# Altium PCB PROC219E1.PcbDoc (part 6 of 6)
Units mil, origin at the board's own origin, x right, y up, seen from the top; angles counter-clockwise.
Board outline 5354.33 x 5354.33 mil, 4 copper layers (Top Layer, Inner Layer 1, Inner Layer 2, Bottom Layer), stack 62.449 mil thick; 579 components, 299 nets, 1709 pads, 802 vias.
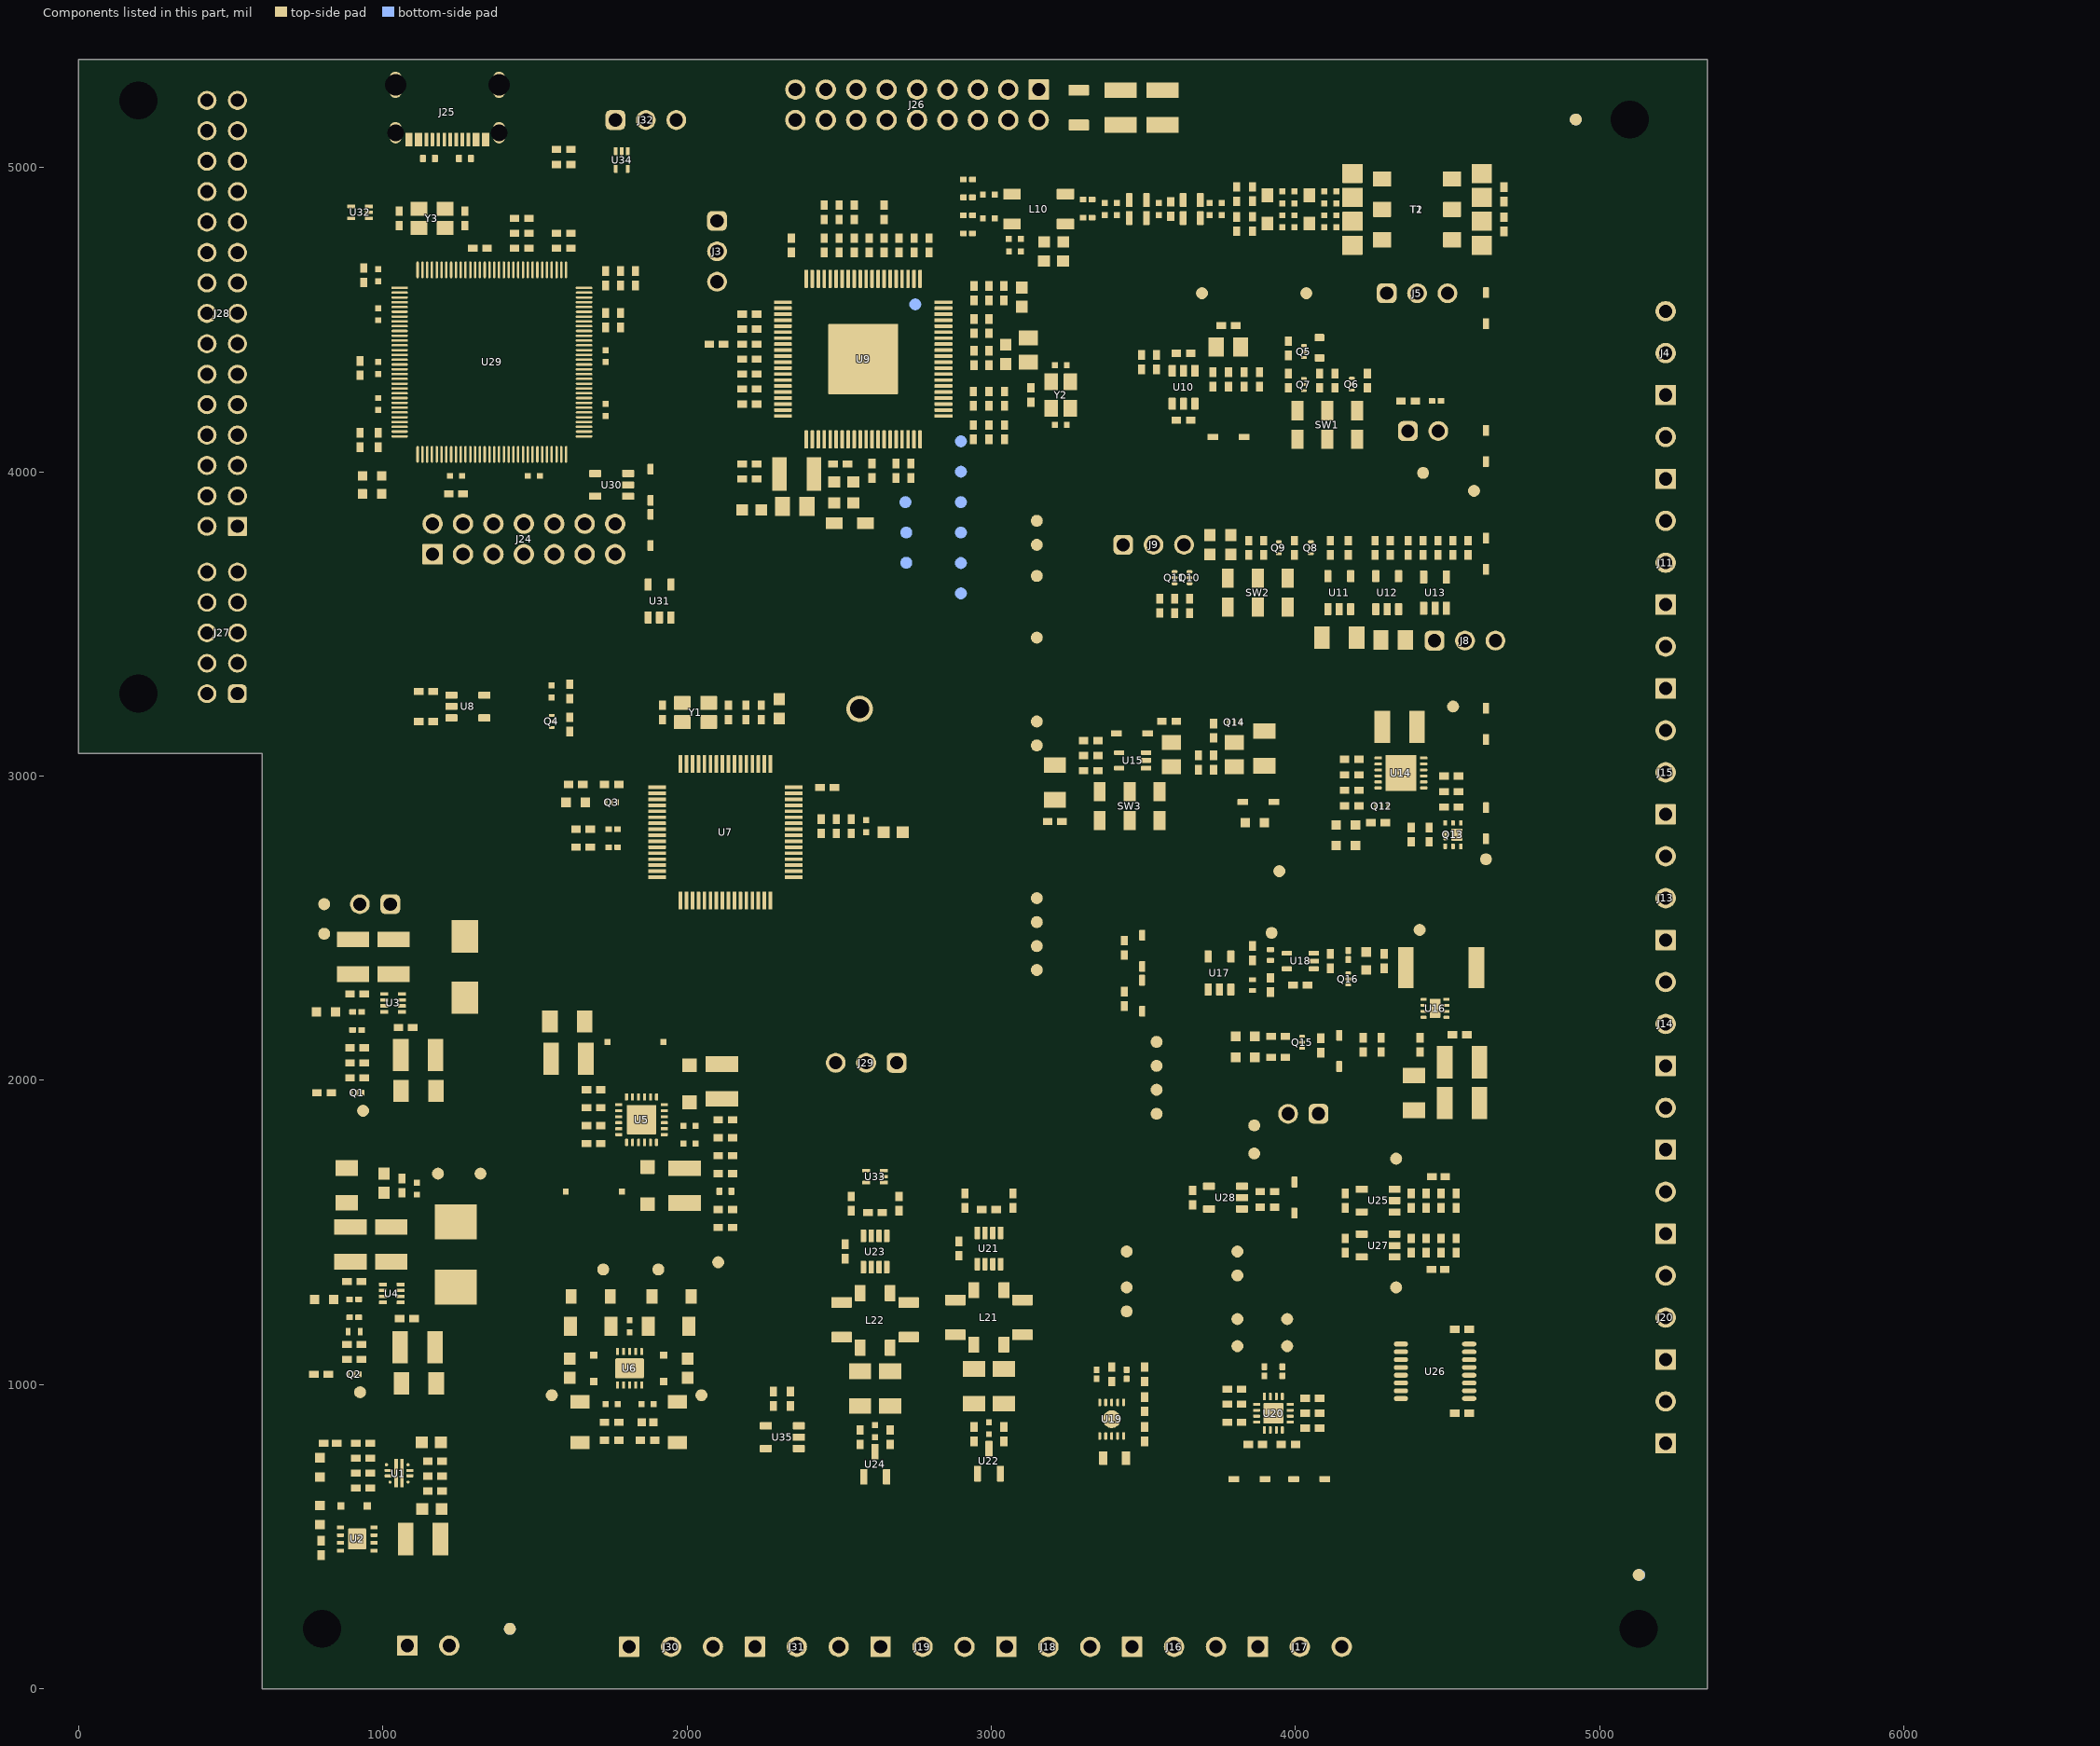
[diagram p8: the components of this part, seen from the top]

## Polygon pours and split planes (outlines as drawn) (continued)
+14V_EXT on Top Layer "TOP_LAYER_+14V_EXT_P077" (solid, remove dead copper, pour order 77): 1862.2,1090.55 1870.08,1082.68 1940.94,1082.68 1940.94,1393.7 1933.07,1401.64 1838.65,1401.64 1830.71,1393.7 1830.71,1149.61 1822.83,1141.73 1822.83,1090.55 1822.83,1141.73 1822.83,1090.55
-14V_EXT on Top Layer "TOP_LAYER_-14V_EXT_P075" (solid, remove dead copper, pour order 75): 1783.68,1091.09 1760.38,1091.09 1751.97,1082.68 1677.17,1082.68 1677.17,1393.7 1685.04,1401.57 1775.59,1401.57 1783.46,1393.7 1783.46,1090.55
NetD11_1 on Top Layer "TOP_LAYER_NETD11_1_P072" (solid, remove dead copper, pour order 72): 1830.56,1812.2 1795.12,1812.2 1720.32,1737.4 1720.32,1528.73 1887.42,1528.73 1897.48,1538.79 1897.48,1615.35 1830.56,1682.28
NetD7_2 on Top Layer "TOP_LAYER_NETD7_2_P070" (solid, remove dead copper, pour order 70): 1909.3,1910.62 1889.61,1930.31 1889.61,1979.52 1860.08,2009.05 1860.08,2235.43 1948.67,2235.43 2037.25,2146.85 2037.25,2015.25 1932.62,1910.62
NetC28_2 on Top Layer "TOP_LAYER_NETC28_2_P063" (solid, remove dead copper, pour order 63): 1830.56,1961.86 1823.59,1968.83 1823.59,2232.55 1820.71,2235.43 1623.86,2235.43 1623.86,1999.21 1633.71,1989.36 1682.92,1989.36 1692.76,1979.52 1692.76,1890.94 1751.82,1890.94 1751.82,1930.31 1830.56,1930.31
5V on Top Layer "TOP_LAYER_5V_P015" (solid, remove dead copper, pour order 15): 984.25,2539.37 984.25,2618.11 856.3,2618.11 856.3,2389.58 1318.9,2389.58 1318.9,2539.37
NetC8_2 on Top Layer "TOP_LAYER_NETC8_2_P036" (solid, remove dead copper, pour order 36): 1047.24,2273.62 1047.24,2253.94 1096.46,2253.94 1135.83,2214.57 1312.99,2214.57 1312.99,2332.68 1135.83,2332.68 1076.77,2273.62
NetC9_2 on Top Layer "TOP_LAYER_NETC9_2_P062" (solid, remove dead copper, pour order 62): 1147.75,1925.42 1147.75,1995.95 1086.61,2057.09 1086.61,2185.04 1076.77,2234.25 1047.24,2234.25 1047.24,2253.94 1092.45,2253.94 1234.25,2112.14 1234.25,2017.72 1234.25,1925.42
3.3V on Top Layer "TOP_LAYER_3.3V_P017" (solid, remove dead copper, pour order 17): 842.52,1653.54 1112.2,1653.54 1151.57,1614.17 1230.32,1614.17 1230.32,1740.16 842.52,1740.16
3V3_FB on Top Layer "TOP_LAYER_3V3_FB_P060" (solid, remove dead copper, pour order 60): 1318.9,1437.01 838.58,1437.01 838.58,1625.98 933.07,1625.98 974.41,1584.65 1082.68,1584.65 1092.52,1594.49 1318.9,1594.49
NetC13_2 on Top Layer "TOP_LAYER_NETC13_2_P058" (solid, remove dead copper, pour order 58): 1043.31,1318.9 1043.31,1299.21 1092.52,1299.21 1131.89,1259.84 1309.06,1259.84 1309.06,1377.95 1131.89,1377.95 1072.83,1318.9
12V on Top Layer "TOP_LAYER_12V_P057" (solid, remove dead copper, pour order 57): 1074.8,661.42 1055.12,661.42 1055.12,755.91 1051.18,759.84 1011.81,759.84 984.25,787.4 984.25,1023.62 1003.94,1043.31 1131.89,1043.31 1151.57,1023.62 1151.57,836.61 1151.57,787.4 1128.61,759.84 1078.74,759.84 1074.8,755.91
+12Va on Inner Layer 2 "INNER_LAYER_2_+12VA_P064" (solid, remove dead copper, pour order 64): 2007.87,767.72 1998.03,757.87 1998.03,688.98 2007.87,679.13 2066.93,679.13 2076.77,688.98 2076.77,757.87 2066.93,767.72
-12Va on Inner Layer 2 "INNER_LAYER_2_-12VA_P065" (solid, remove dead copper, pour order 65): 1546.79,720.02 1525.59,698.82 1525.59,649.61 1545.28,629.92 1594.49,629.92 1624.02,659.45 1624.02,679.13 1583.13,720.02
+12Va on Inner Layer 2 "INNER_LAYER_2_+12VA_P074" (solid, remove dead copper, pour order 74): 4381.17,3347.61 4244.53,3484.25 4104.33,3484.25 3996.06,3592.52 3996.06,3779.53 4015.75,3799.21 4378.38,3799.21 4381.17,3796.42
3.3V on Inner Layer 2 "INNER_LAYER_2_3.3V_P093" (solid, remove dead copper, pour order 93): 1259.84,1830.71 1214.74,1787.6 1137.99,1787.6 1122.05,1771.65 1122.05,1604.33 1141.73,1584.65 1230.31,1584.65 1259.84,1555.12 1279.53,1555.12 1279.53,1830.71
NetC50_1 on Inner Layer 2 "INNER_LAYER_2_NETC50_1_P101" (solid, remove dead copper, pour order 101): 3098.43,4696.85 3110.24,4685.04 3295.28,4685.04 3307.09,4696.85 3307.09,4968.5 3299.21,4976.38 3106.3,4976.38 3098.43,4968.5
VDD_CORE_1V1 on Inner Layer 2 "INNER_LAYER_2_VDD_CORE_1V1_P103" (solid, remove dead copper, pour order 103): 2421.26,4704.72 2431.1,4694.88 2431.1,4675.2 2440.94,4665.35 2480.31,4665.35 2490.16,4675.2 2490.16,4694.88 2500,4704.72 2779.53,4704.72 2799.21,4685.04 2799.21,4279.53 2834.65,4244.09 3098.43,4244.09 3110.24,4232.28 3110.24,4114.17 3070.87,4074.8 2688.98,4074.8 2665.35,4051.18 2665.35,3956.69 2350.39,3956.69 2291.34,3897.64 2216.54,3897.64 2216.54,4586.61 2334.65,4704.72
5V on Inner Layer 2 "Mid Layer 2-5V" (solid, remove dead copper, pour order 96): 4438.98,925.2 4429.13,925.2 4192.91,688.98 3149.61,688.98 3149.61,1624.02 2893.7,1624.02 2893.7,1397.64 2883.86,1387.8 2854.33,1387.8 2844.49,1397.64 2844.49,1614.17 2834.65,1624.02 2539.37,1624.02 2539.37,944.88 1250,944.88 1250,2116.14 1614.17,2116.14 1633.86,2135.83 1633.86,2224.41 1614.17,2244.09 1250,2244.09 1250,2578.74 1181.1,2647.64 603.15,2647.64 603.15,0 5354.33,0 5354.33,5354.33 2903.12,5354.33 2903.12,5196.85 3001.97,5196.85 3001.97,5019.69 4438.98,5019.69
3.3V on Inner Layer 2 "INNER_LAYER_2_3.3V_P105" (solid, remove dead copper, pour order 105): 5352.55,5355.14 5354.33,5353.36 5354.33,0 603.15,0 603.15,3073.62 0,3073.62 0,5354.33 5354.33,5354.33
GND on Bottom Layer "BOTTOM_LAYER_GND_P097" (solid, remove dead copper, pour order 97): 5354.33,5354.33 5354.33,0 600.68,0 600.68,3073.62 0,3073.62 0,5354.33
12V on Bottom Layer "BOTTOM_LAYER_12V_P081" (solid, remove dead copper, pour order 81): 4734.25,1013.78 4665.35,1082.68 4488.19,1082.68 4478.35,1092.52 4478.35,1151.57 4488.19,1161.42 4665.35,1161.42 4734.25,1230.31 4734.25,1722.44 4714.57,1742.13 4212.6,1742.13 4183.07,1771.65 4183.07,1919.29 4212.6,1948.82 4655.51,1948.82 4675.2,1968.5 4675.2,2755.91 4625.98,2805.12 3513.78,2805.12 3454.72,2864.17 3454.72,3267.72 3484.25,3297.24 4635.83,3297.24 4744.09,3405.51 4744.09,4891.73 4714.57,4921.26 3405.51,4921.26 3366.14,4960.63 3366.14,5177.17 3395.67,5206.69 4872.05,5206.69 5118.11,4960.63 5118.11,2273.62 5137.8,2253.94 5236.22,2253.94 5265.75,2224.41 5265.75,2135.83 5236.22,2106.3 5137.8,2106.3 5118.11,2086.61 5118.11,482.28 4891.73,255.91 2007.87,255.91 1850.39,98.43 1643.7,98.43 984.25,757.87 984.25,2017.72 994.09,2027.56 1279.53,2027.56 1299.21,2007.87 1299.21,1003.94 1683.07,620.08 4616.14,620.08 4734.25,738.19
NetC4_2 on Bottom Layer "BOTTOM_LAYER_NETC4_2_P040" (solid, remove dead copper, pour order 40): 1151.57,580.71 1151.57,118.11 1131.89,98.43 974.41,98.43 954.72,118.11 954.72,631.02 974.41,653.54 1027.56,653.54 1059.06,653.54 1078.74,653.54
+14V_EXT on Bottom Layer "BOTTOM_LAYER_+14V_EXT_P042" (solid, remove dead copper, pour order 42): 1858.27,1271.65 1862.2,1267.72 1940.94,1267.72 1944.88,1271.65 1944.88,1389.99 1940.94,1393.93 1862.2,1393.93 1858.27,1389.99
-14V_EXT on Bottom Layer "BOTTOM_LAYER_-14V_EXT_P039" (solid, remove dead copper, pour order 39): 1685.04,1275.59 1688.98,1271.65 1759.84,1271.65 1763.78,1275.59 1763.78,1393.7 1759.84,1397.64 1688.98,1397.64 1685.04,1393.7
GND on Inner Layer 1 "INNER_LAYER_1_GND_P098" (solid, remove dead copper, pour order 98): 5352.55,5355.14 5354.33,5353.36 5354.33,0 603.15,0 603.15,3073.62 0,3073.62 0,5354.33 5354.33,5354.33

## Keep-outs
Keep-Out Layer:
  text ".Layer_Name" at 577,-858.49 h60

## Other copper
Top Layer:
  text ".Layer_Name" at 577,-858.49 h60
Bottom Layer:
  text ".Layer_Name" at 577,-858.49 h60

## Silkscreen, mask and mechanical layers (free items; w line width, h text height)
Top Overlay:
  drawing of 4544 lines, arcs and shapes, not listed
  text ".PRJ_Title" at 225.17,4780.19 h108.27 r270
  text "CCS CP" at 4755.12,4504.43 h39.37
  text "EVSE" at 4282.93,4483.03 h30
  text "EV" at 4445.29,4483.03 h30
  text "CCS PE" at 4755.12,4366.64 h39.37
  text "CCS PP" at 4755.12,4228.84 h39.37
  text "GB/T CC1" at 4755.12,4093.86 h39.37
  text "Plug In" at 3930.62,3986.07 h30
  text "GB/T PE" at 4755.12,3956.06 h39.37
  text "CCS" at 3930.62,3935.79 h30
  text "CDM CS1" at 4755.12,3815.46 h39.37
  text "CDM CS2" at 4755.12,3677.66 h39.37
  text "<<TXD" at 1445.67,3637.67 h35.43 r270
  text ">>RXD" at 1345.67,3637.16 h35.43 r270
  text "SWCLK" at 1745.67,3634.38 h35.43 r270
  text "SWDIO" at 1645.67,3625.86 h35.43 r270
  text "nRST" at 1545.67,3610.42 h35.43 r270
  text "CDM CP" at 4755.12,3539.87 h39.37
  text "Plug In" at 3702.27,3425.04 h30
  text "CDM PD" at 4755.12,3402.07 h39.37
  text "GB/T" at 3702.89,3370.83 h30
  text "EVSE" at 4440.41,3341.3 h30
  text "EV" at 4602.77,3341.3 h30
  text "CDM PE" at 4755.12,3264.28 h39.37
  text "PTC 1" at 4755.12,3126.48 h39.37
  text "PTC 2" at 4755.12,2988.69 h39.37
  text "PTC GND" at 4755.12,2850.89 h39.37
  text "Plug In" at 3281.02,2726.22 h30
  text "LO - CDM" at 4755.12,2713.09 h39.37
  text "CHAdeMO" at 3281.02,2672.01 h30
  text "LO -" at 4755.12,2575.3 h39.37
  text "LO +" at 4755.12,2437.5 h39.37
  text "LO FB" at 4755.12,2299.71 h39.37
  text "'.PRJ_Number'.PCB_Rev" at 2236.22,2244.09 h108.27
  text "LO 12V" at 4755.12,2161.91 h39.37
  text "LO GND" at 4755.12,2025.1 h39.37
  text "CAN 2" at 2771.19,1982.48 h35.43 r270
  text "<<RX" at 2570.87,1956.28 h35.43 r270
  text ">>TX" at 2672.45,1953.6 h35.43 r270
  text "IO IN 1" at 4755.12,1887.31 h39.37
  text "IO IN 2" at 4755.12,1749.51 h39.37
  text "IO IN 3" at 4755.12,1611.72 h39.37
  text "IO GND" at 4755.12,1473.92 h39.37
  text "IO OUT 1" at 4755.12,1336.13 h39.37
  text "IO OUT 2" at 4755.12,1198.33 h39.37
  text "IO OUT 3" at 4755.12,1060.54 h39.37
  text "IO COM" at 4755.12,922.74 h39.37
  text "IO GND" at 4755.12,784.95 h39.37
  text "RCD 12V" at 1789.77,599.21 h39.37 r270
  text "RCD GND" at 1927.56,599.21 h39.37 r270
  text "RCD ER" at 2065.36,599.21 h39.37 r270
  text "RCD RST" at 2203.15,599.21 h39.37 r270
  text "RCD TST" at 2340.95,599.21 h39.37 r270
  text "RCD nER" at 2478.74,599.21 h39.37 r270
  text "CAN GND" at 2616.54,599.21 h39.37 r270
  text "CAN2 N" at 2754.33,599.21 h39.37 r270
  text "CAN2 P" at 2892.13,599.21 h39.37 r270
  text "CAN GND" at 3029.93,599.21 h39.37 r270
  text "CAN1 N" at 3167.72,599.21 h39.37 r270
  text "CAN1 P" at 3305.52,599.21 h39.37 r270
  text "RS GND" at 3443.31,599.21 h39.37 r270
  text "RS485 P" at 3581.11,599.21 h39.37 r270
  text "RS485 N" at 3718.9,599.21 h39.37 r270
  text "RS GND" at 3856.7,599.21 h39.37 r270
  text "RS232 TX" at 3994.49,599.21 h39.37 r270
  text "RS232 RX" at 4132.29,599.21 h39.37 r270
  text "12V" at 854.46,24.22 h50
  text "GND" at 1346.58,24.22 h50
  text ".Layer_Name" at 577,-858.49 h60
Bottom Overlay:
  text ".Layer_Name" at 577,-858.49 h60
Top Paste:
  text ".Layer_Name" at 577,-858.49 h60
Bottom Paste:
  text ".Layer_Name" at 577,-858.49 h60
Top Solder:
  text ".Layer_Name" at 577,-858.49 h60
  text ".Layer_Name" at 577,-858.49 h60
Bottom Solder:
  text ".Layer_Name" at 577,-858.49 h60
Drill Guide:
  text ".Layer_Name" at 577,-858.49 h60
M1 Board Outline:
  the board outline again, w10
  text ".Layer_Name" at 577,-858.49 h60
M2 Board Dimensions:
  rectangle: 0,-275 125,-150
  rectangle: 125,-400 500,-275
  lines w7: 0,-275 1000,-275 ; 125,-400 125,-150 ; 250,-400 250,-150 ; 500,-400 500,-150 ; 750,-400 750,-150 ; 0,-400 1000,-400 1000,-150 0,-150 0,-400
  text ".Layer_Name" at 577,-858.49 h60
M3 3D STEP Top:
  text ".Layer_Name" at 577,-858.49 h60
M4 3D STEP Bottom:
  text ".Layer_Name" at 577,-858.49 h60
M5 Assembly Top:
  lines w10: -292,-930.17 6308,-930.17 ; -292,-726.83 6310,-726.83 ; -292,-523.5 -292,-1133.5 3713,-1133.5 6310,-1133.5 6310,-523.5 -291.5,-523.5 -291.5,-1133.5 1284,-1133.5 ; 2173,-1133.5 2173,-523.5 ; 3440,-726.83 3440,-523.5 ; 4280,-726.83 4280,-523.5 ; 4902,-1140 4902,-937.17
  text "COMPONENTS MARKED 'DNP' SHOULD NOT BE POPULATED." at 1153.5,-318.5 h60
  text "ASSEMBLY VARIANT:" at 1153,-434 h60
  text ".VariantName" at 2189,-434 h60
  text "PCB VIEWED FROM TOP SIDE" at -228.5,-655.67 h60
  text "BOARD #:" at 2248,-655.67 h60
  text ".PRJ_Number" at 2793.5,-655.67 h60
  text "REV:" at 3638,-655.67 h60
  text ".PCB_Rev" at 3929.5,-655.67 h60
  text "SVN REV:" at 4476,-655.67 h60
  text ".VersionControl_RevNumber" at 4982,-655.67 h60
  text "TID #:" at 2248,-859 h60
  text ".TID" at 2793.5,-859 h60
  text "PLOT NAME =" at -228.5,-1064.34 h60
  text ".plot_File_Name" at 577,-1064.34 h60
  text "GENERATED    :" at 2250,-1064.34 h60
  text ".Print_Date" at 3119.5,-1064.34 h60
  text ".Print_Time" at 3848.5,-1064.34 h60
  text "TEXAS INSTRUMENTS" at 5113,-1064.34 h60
M6 Assembly Bottom:
  lines w10: -292.5,-727.33 6309.5,-727.33 ; -290.5,-930.67 6309.5,-930.67 ; 1115.5,-1140.5 1115.5,-937.67 ; 1737.5,-727.33 1737.5,-524 ; 2577.5,-727.33 2577.5,-524 ; 3844.5,-1134 3844.5,-524 ; 4733.5,-1134 6309,-1134 6309,-524 -292.5,-524 -292.5,-1134 2304.5,-1134 6309.5,-1134 6309.5,-524
  text "COMPONENTS MARKED 'DNP' SHOULD NOT BE POPULATED." at 6102,-318 h60
  text ".VariantName" at 5058,-434 h60
  text "ASSEMBLY VARIANT:" at 6097,-434 h60
  text ".VersionControl_RevNumber" at 1035.5,-656.17 h60
  text "SVN REV:" at 1541.5,-656.17 h60
  text ".PCB_Rev" at 2088,-656.17 h60
  text "REV:" at 2379.5,-656.17 h60
  text ".PRJ_Number" at 3224,-656.17 h60
  text "BOARD #:" at 3769.5,-656.17 h60
  text "PCB VIEWED FROM BOTTOM SIDE" at 6246,-656.17 h60
  text ".TID" at 3224,-859.5 h60
  text "TID #:" at 3769.5,-859.5 h60
  text "TEXAS INSTRUMENTS" at 904.5,-1064.84 h60
  text ".Print_Time" at 2169,-1064.84 h60
  text ".Print_Date" at 2898,-1064.84 h60
  text "GENERATED    :" at 3767.5,-1064.84 h60
  text ".plot_File_Name" at 5440.5,-1064.84 h60
  text "PLOT NAME =" at 6246,-1064.84 h60
M9 Title Sheet:
  drawing of 57 lines, arcs and shapes, not listed
  text "1" at 739.84,8036.5 h70
  text "2" at 3235.5,8036.5 h70
  text "3" at 5724.84,8036.5 h70
  text "4" at 8231.51,8036.5 h70
  text "5" at 10730.5,8036.5 h70
  text "6" at 13235.5,8036.5 h70
  text "A" at -416.5,6893.5 h70
  text "A" at 14383.5,6893.5 h70
  text "B" at -416.5,4513.5 h70
  text "B" at 14383.5,4513.5 h70
  text "C" at -416.5,2138.5 h70
  text "C" at 14383.5,2138.5 h70
  text "PROJECT TITLE:" at 11343.5,277.5 h45
  text ".PRJ_Title" at 11393.5,144.17 h70
  text "DESIGNED FOR:" at 11343.5,-23.5 h45
  text ".PRJ_Customer" at 11393.5,-163.5 h70
  text "D" at -416.5,-231.5 h70
  text "D" at 14383.5,-231.5 h70
  text "FILE NAME:" at 11343.5,-323.5 h45
  text ".PCB_File_Name_No_Path" at 11393.5,-443.5 h70
  text "Texas Instruments (TI) and/or its licensors do not warrant the accuracy or completeness of this specification" at 6374,-605.34 h45
  text "ENGINEER:" at 11343.5,-613.5 h45
  text "LAYOUT BY:" at 12848.5,-613.5 h45
  text "or any information contained therein. TI and/or its licensors do not warrant that this design will meet" at 6329.01,-718 h45
  text ".PRJ_Engineer" at 11393.5,-768.49 h70
  text ".PCB_Layout" at 12899,-768.49 h70
  text "the specifications, will be suitable for your application or fit for any particular purpose, or will operate in" at 6329.01,-830.67 h45
  text ".Layer_Name" at 577,-858.49 h60
  text "ALTIUM DESIGNER VERSION:" at 12848.5,-923.5 h45
  text "an implementation. TI and/or its licensors do not warrant that the design is production worthy. You should" at 6329.01,-943.33 h45
  text "completely validate and test your design implementation to confirm the system functionality for your application." at 6374,-1056 h45
  text ".print_Scale" at 11393.5,-1056.83 h70
  text ".Application_BuildNumber" at 12899,-1056.83 h70
  text "1" at 739.84,-1263.5 h70
  text "2" at 3235.5,-1263.5 h70
  text "3" at 5724.84,-1263.5 h70
  text "4" at 8231.51,-1263.5 h70
  text "5" at 10730.5,-1263.5 h70
  text "6" at 13235.5,-1263.5 h70
M10 Fab Notes:
  drawing of 189 lines, arcs and shapes, not listed
  text "DESIGN INFORMATION" at 12382.02,6356.17 h60
  text "MIN. TRACK WIDTH:" at 11737.46,6224.05 h60
  text "6" at 12833.7,6224.05 h60
  text "MIL" at 12988.46,6224.05 h60
  text "4" at 12834.65,6102.36 h60
  text "MIN. CLEARANCE:" at 11737.46,6099.92 h60
  text "MIL" at 12988.46,6099.92 h60
  text "MIN. VIA PAD SIZE:" at 11737.46,5975.8 h60
  text "24" at 12803.71,5975.8 h60
  text "MIL" at 12988.46,5975.8 h60
  text "0.05mm (2MIL)" at 12432.46,5845.9 h60
  text "MINIMUM ANNULAR RING" at 11408.23,5837.67 h60
  text "EXTERNAL" at 13140.46,5837.67 h60
  text "PER" at 11608.23,5727.55 h60
  text "IPC-D-275 CLASS 2 LEVEL C" at 11828.23,5727.54 h60
  text "MIL, HOLES" at 13316.46,5627.07 h60
  text "+/-" at 12924,5618.48 h60
  text "+/-" at 13778,5618.48 h60
  text "REGISTRATION TOLERANCES:" at 11408.23,5617.42 h60
  text "METAL" at 12608,5617.42 h60
  text "5" at 13184.2,5617.42 h60
  text "3" at 14017.2,5617.42 h60
  text "MIL" at 14133.46,5617.42 h60
  text "HOLE SIZE TOLERANCE (UNLESS OTHERWISE SPECIFIED):" at 11408.23,5519.1 h60
  text "+/-" at 13778,5516.23 h60
  text "3" at 14017.2,5515.17 h60
  text "MIL" at 14133.46,5515.17 h60
  text "MATERIAL:" at 11333.46,5377.52 h60
  text "FR-4 High Tg" at 12319.9,5249 h60
  text "X" at 12175.46,5241.01 h60
  text "FR-4" at 11754.46,5236.49 h60
  text "OTHER" at 13242.46,5236.49 h60
  text "62 MIL (1.6mm) +/-10%" at 12074.56,5093.46 h60
  text "X" at 11954.46,5091.01 h60
  text "THICKNESS:" at 11408.23,5085.24 h60
  text "OTHER" at 13359.46,5085.24 h60
  text "TOLERANCE:" at 11408.23,4946.92 h60
  text "X" at 12256.46,4946.92 h60
  text "ANSI IPC-6012 TYPE 3 CLASS 2" at 12434.48,4946.92 h60
  text "OTHER +/-" at 12434.46,4802.73 h60
  text "BOW & TWIST:" at 11408.23,4657.54 h60
  text "X" at 12256.46,4657.54 h60
  text "ANSI IPC-6012 TYPE 3 CLASS 2" at 12434.48,4657.54 h60
  text "OTHER +/-" at 12434.46,4510.85 h60
  text "DRILLING:" at 11333.46,4380.23 h60
  text "NC_DRILL FILES" at 13094.46,4275.04 h60
  text "REFERENCE:" at 11408.23,4271.1 h60
  text "X" at 12065.46,4271.01 h60
  text "AS SHOWN" at 12243.46,4271.1 h60
  text "X" at 12966.46,4271.1 h60
  text "OTHER" at 13392.46,4128.85 h60
  text "PTH COPPER THICKNESS:" at 11407.91,4125.32 h60
  text "X" at 12547.14,4125.32 h60
  text "20-30 um" at 12675.14,4125.32 h60
  text "BOARD FINISH:" at 11333.46,3977.73 h60
  text "SILKSCREEN:" at 11488.68,3867.6 h60
  text "X" at 12446.46,3867.6 h60
  text "TOP" at 12563.46,3867.6 h60
  text "X" at 12956.46,3867.6 h60
  text "BOTTOM" at 13074.46,3867.6 h60
  text "SILKSCREEN COLOR:" at 11488.68,3712.41 h60
  text "X" at 12445.46,3712.41 h60
  text "WHITE" at 12563.46,3712.41 h60
  text "OTHER" at 13074.46,3712.41 h60
  text "X" at 12576.46,3568.96 h60
  text "GREEN" at 12694.46,3568.96 h60
  text "OTHER" at 13312.46,3568.96 h60
  text "SOLDER RESIST COLOR:" at 11488.68,3562.1 h60
  text "X" at 12576.46,3414.71 h60
  text "MATTE" at 12694.46,3414.71 h60
  text "SEMI-GLOSS" at 13312,3414.07 h60
  text "IMMERSION GOLD (ENIG)" at 12394.46,3241.94 h60
  text "ENEPIG" at 13732,3234.72 h60
  text "SURFACE FINISH:" at 11333.46,3233.72 h60
  text "X" at 12216.46,3233.72 h60
  text "IMM. TIN/SILVER OR EQUIV" at 11663,3096.4 h60
  text "OTHER" at 13094.46,3092.47 h60
  text "ARRAY/PANEL:" at 11333.46,2937.09 h60
  text "CUT AND TRIM PER M1 BOARD OUTLINE" at 12394.46,2928.87 h60
  text "N.C. ROUTE" at 12394.46,2792.9 h60
  text "X" at 13082.46,2792.9 h60
  text "V. SCORE" at 13260.46,2792.9 h60
  text "CERTIFICATION:" at 11333.46,2663.77 h60
  text "MATERIALS AND WORKMANSHIP FOR ALL PCBS" at 12058.46,2663.77 h60
  text "TO MEET OR EXCEED THE REQUIREMENTS OF:" at 12058.46,2569.71 h60
  text "X" at 11695.97,2441.08 h60
  text "ANSI IPC-A-600F CLASS ->" at 11823.96,2441.08 h60
  text "X" at 13471.97,2441.08 h60
  text "2" at 13581.96,2441.08 h60
  text "1" at 13266.96,2439.58 h60
  text "3" at 13935.96,2439.58 h60
  text "X" at 12507.97,2293.39 h60
  text "RoHS" at 12635.96,2293.39 h60
  text "OTHER" at 13280.36,2293.39 h60
  text "PER ORDER" at 13677.42,2293.39 h60
  text "ALL BOARDS MUST MEET OR EXCEED UL94-V0 REQUIREMENTS." at 11361,2139.57 h60
  text "PCB MUST BEAR THE UL94V-0 UL REGISTERED MATERIAL ID NUMBER" at 11361,2023.5 h60
  text "ADDITIONAL REQUIREMENTS:" at 11333.46,1854.08 h60
  text "MICROSECTION:" at 11408.23,1746.95 h60
  text "YES" at 12313.96,1746.95 h60
  text "REQUIRED" at 13175.46,1602.62 h60
  text "BARE BOARD ELEC. TEST:" at 11408.23,1599.76 h60
  text "NONE" at 12713.96,1599.76 h60
  text "X" at 13057.46,1599.76 h60
  text "PER ORDER" at 13767.46,1599.76 h60
  text "XX MIL VIAS REQUIRE NON-CONDUCTIVE FILL AND PLANARIZE" at 11576.38,1394.82 h59
  text "XX MIL VIAS REQUIRE CONDUCTIVE FILL AND PLANARIZE" at 11584.38,1290.84 h60
  text "OUTER XX MIL TRACES REQUIRE 50 OHM SINGLE-ENDED IMPEDANCE" at 11583.39,1127.46 h58
  text "LAYER 2 & 3 (INNER LAYERS) XX MIL WIDE, XX MIL SPACE / TRACES REQUIRE 100 OHM DIFFERENTIAL IMPEDANCE" at 11575.39,891.74 h60
  text ".Layer_Name" at 577,-858.49 h60
M11 Gerber Information:
  lines w10: -292,-930.17 6308,-930.17 ; -292,-726.83 6310,-726.83 ; -292,-523.5 -292,-1133.5 3713,-1133.5 6310,-1133.5 6310,-523.5 -291.5,-523.5 -291.5,-1133.5 1284,-1133.5 ; 2173,-1133.5 2173,-523.5 ; 3440,-726.83 3440,-523.5 ; 4280,-726.83 4280,-523.5 ; 4902,-1140 4902,-937.17
  text "ALL ARTWORK VIEWED FROM TOP SIDE" at -228.5,-655.67 h60
  text "BOARD #:" at 2248,-655.67 h60
  text ".PRJ_Number" at 2793.5,-655.67 h60
  text "REV:" at 3638,-655.67 h60
  text ".PCB_Rev" at 3929.5,-655.67 h60
  text "SVN REV:" at 4476,-655.67 h60
  text ".VersionControl_RevNumber" at 4982,-655.67 h60
  text "LAYER NAME =" at -228.5,-858.49 h60
  text "TID #:" at 2248,-859 h60
  text ".TID" at 2793.5,-859 h60
  text "PLOT NAME =" at -228.5,-1064.34 h60
  text ".plot_File_Name" at 577,-1064.34 h60
  text "GENERATED    :" at 2250,-1064.34 h60
  text ".Print_Date" at 3119.5,-1064.34 h60
  text ".Print_Time" at 3848.5,-1064.34 h60
  text "TEXAS INSTRUMENTS" at 5113,-1064.34 h60
M12 Stackup:
  drawing of 295 lines, arcs and shapes, not listed
  text "Layer" at 9821.59,7874.94 h60
  text "Name" at 10231.51,7874.94 h60
  text "Material" at 11161.25,7874.94 h60
  text "Thickness" at 12021.02,7874.94 h60
  text "Constant" at 12670.85,7874.94 h60
  text "Board Layer Stack" at 13240.71,7874.94 h60
  text "Top Overlay" at 10231.51,7754.94 h60
  text "Top Solder" at 10231.51,7634.94 h60
  text "Solder Resist" at 11161.25,7634.94 h60
  text "0.60mil" at 12021.02,7634.94 h60
  text "3.8" at 12670.85,7634.94 h60
  text "1" at 9821.59,7514.94 h60
  text "Top Layer" at 10231.51,7514.94 h60
  text "CF-004" at 11161.25,7514.94 h60
  text "1.38mil" at 12021.02,7514.94 h60
  text "Dielectric 1" at 10231.51,7394.94 h60
  text "NP-155F" at 11161.25,7394.94 h60
  text "8.28mil" at 12021.02,7394.94 h60
  text "4.4" at 12670.85,7394.94 h60
  text "2" at 9821.59,7274.94 h60
  text "Inner Layer 1" at 10231.51,7274.94 h60
  text "CF-004" at 11161.25,7274.94 h60
  text "0.60mil" at 12021.02,7274.94 h60
  text "Dielectric 2" at 10231.51,7154.94 h60
  text "NP-155F" at 11161.25,7154.94 h60
  text "41.93mil" at 12021.02,7154.94 h60
  text "4.43" at 12670.85,7154.94 h60
  text "3" at 9821.59,7034.94 h60
  text "Inner Layer 2" at 10231.51,7034.94 h60
  text "CF-004" at 11161.25,7034.94 h60
  text "0.60mil" at 12021.02,7034.94 h60
  text "Dielectric 3" at 10231.51,6914.94 h60
  text "NP-155F" at 11161.25,6914.94 h60
  text "8.28mil" at 12021.02,6914.94 h60
  text "4.4" at 12670.85,6914.94 h60
  text "4" at 9821.59,6794.94 h60
  text "Bottom Layer" at 10231.51,6794.94 h60
  text "CF-004" at 11161.25,6794.94 h60
  text "1.38mil" at 12021.02,6794.94 h60
  text "Bottom Solder" at 10231.51,6674.94 h60
  text "Solder Resist" at 11161.25,6674.94 h60
  text "0.60mil" at 12021.02,6674.94 h60
  text "3.8" at 12670.85,6674.94 h60
  text "Bottom Overlay" at 10231.51,6554.94 h60
  text ".Layer_Name" at 577,-858.49 h60
M13 Component Bodies Top:
  text ".Layer_Name" at 577,-858.49 h60
M14 Component Bodies Bottom:
  text ".Layer_Name" at 577,-858.49 h60
M15 Courtyards Top:
  text ".Layer_Name" at 577,-858.49 h60
M16 Courtyards Bottom:
  text ".Layer_Name" at 577,-858.49 h60
Drill Drawing:
  circle w10: c5859.55,3232.08 r27.63
  lines w10: 5831.92,2720.99 5845.73,2720.99 5845.73,2707.18 5873.36,2707.18 5873.36,2720.99 5887.17,2720.99 5887.17,2748.61 5873.36,2748.61 5873.36,2762.43 5845.73,2762.43 5845.73,2748.61 5831.92,2748.61 5831.92,2720.99 ; 5831.92,2831.49 5831.92,2845.31 5845.73,2859.12 5831.92,2872.94 5831.92,2886.75 5845.73,2886.75 5859.55,2872.94 5873.36,2886.75 5887.17,2886.75 5887.17,2872.94 5873.36,2859.12 5887.17,2845.31 5887.17,2831.49 5873.36,2831.49 5859.55,2845.31 5845.73,2831.49 5831.92,2831.49 ; 5831.92,2969.63 5845.73,2969.63 5859.55,2955.81 5873.36,2969.63 5887.17,2969.63 5873.36,2983.44 5887.17,2997.26 5873.36,2997.26 5859.55,3011.07 5845.73,2997.26 5831.92,2997.26 5845.73,2983.44 5831.92,2969.63 ; 5831.92,3080.14 5887.17,3080.14 5887.17,3135.39 5831.92,3135.39 5831.92,3080.14 ; 5831.92,3328.77 5859.55,3342.59 5887.17,3328.77 5873.36,3356.4 5887.17,3384.03 5859.55,3370.22 5831.92,3384.03 5845.73,3356.4 5831.92,3328.77
  lines w12: 5781.83,2669.88 9013.32,2669.88 ; 5781.83,3415.8 9013.32,3415.8 ; 6119.69,2545.56 6119.69,3540.12 ; 6451.69,2545.56 6451.69,3540.12 ; 7088.26,2545.56 7088.26,3540.12 ; 7347.4,2545.56 7347.4,3540.12 ; 7722.55,2545.56 7722.55,3540.12 ; 8446.89,2545.56 8446.89,3540.12 ; 5781.83,2545.56 9013.32,2545.56 9013.32,3540.12 5781.83,3540.12 5781.83,2545.56
  text "Symbol" at 5856.42,3453.1 h72
  text "Quantity" at 6156.99,3453.1 h72
  text "Finished Hole Size" at 6488.99,3453.1 h72
  text "Plated" at 7125.55,3453.1 h72
  text "Hole Type" at 7384.69,3453.1 h72
  text "Drill Layer Pair" at 7759.85,3453.1 h72
  text "Hole Tolerance" at 8484.18,3453.1 h72
  text "5" at 6156.99,3328.77 h60
  text "125.00mil (3.175mm)" at 6488.99,3328.77 h60
  text "NPTH" at 7125.55,3328.77 h60
  text "Round" at 7384.69,3328.77 h60
  text "Top Layer - Bottom Layer" at 7759.85,3328.77 h60
  text "802" at 6156.99,3204.45 h60
  text "11.81mil (0.300mm)" at 6488.99,3204.45 h60
  text "PTH" at 7125.55,3204.45 h60
  text "Round" at 7384.69,3204.45 h60
  text "Top Layer - Bottom Layer" at 7759.85,3204.45 h60
  text "144" at 6156.99,3080.14 h60
  text "43.31mil (1.100mm)" at 6488.99,3080.14 h60
  text "PTH" at 7125.55,3080.14 h60
  text "Round" at 7384.69,3080.14 h60
  text "Top Layer - Bottom Layer" at 7759.85,3080.14 h60
  text "1" at 6156.99,2955.81 h60
  text "63.00mil (1.600mm)" at 6488.99,2955.81 h60
  text "PTH" at 7125.55,2955.81 h60
  text "Round" at 7384.69,2955.81 h60
  text "Top Layer - Bottom Layer" at 7759.85,2955.81 h60
  text "2" at 6156.99,2831.49 h60
  text "55.12mil (1.400mm)" at 6488.99,2831.49 h60
  text "PTH" at 7125.55,2831.49 h60
  text "Slot" at 7384.69,2831.49 h60
  text "Top Layer - Bottom Layer" at 7759.85,2831.49 h60
  text "2" at 6156.99,2707.18 h60
  text "70.87mil (1.800mm)" at 6488.99,2707.18 h60
  text "PTH" at 7125.55,2707.18 h60
  text "Slot" at 7384.69,2707.18 h60
  text "Top Layer - Bottom Layer" at 7759.85,2707.18 h60
  text "956 Total" at 6156.99,2582.85 h60
  text "Slot definitions :" at 5856.42,2495.83 h60
  text "Routed Path Length" at 6307.14,2495.83 h60
  text "= Calculated from tool start centre position to tool end centre position." at 6846.88,2495.83 h60
  text "Hole Length" at 6307.14,2446.1 h60
  text "= Routed Path Length + Tool Size = Slot length as defined in the PCB layout" at 6647.08,2446.1 h60
  text ".Layer_Name" at 577,-858.49 h60
M17 Embedded Cavity:
  text ".Layer_Name" at 577,-858.49 h60
M18 Embedded Assembly:
  text ".Layer_Name" at 577,-858.49 h60
M19 Embedded Keepout:
  text ".Layer_Name" at 577,-858.49 h60

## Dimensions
0,-400 to 1000,-400 on M2 Board Dimensions
0,0 to 0,5354.33 on M2 Board Dimensions
5354.33,0 to 0,3073.62 on M2 Board Dimensions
